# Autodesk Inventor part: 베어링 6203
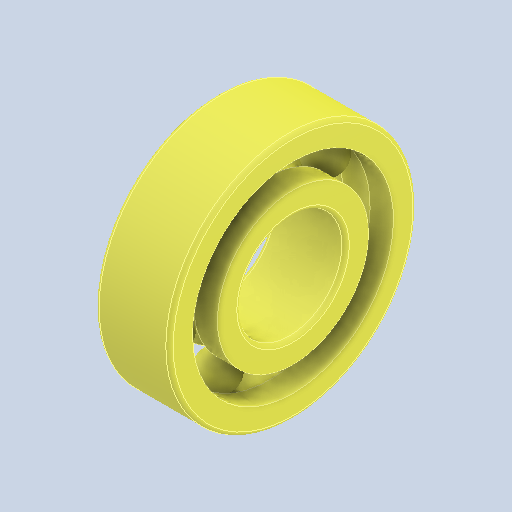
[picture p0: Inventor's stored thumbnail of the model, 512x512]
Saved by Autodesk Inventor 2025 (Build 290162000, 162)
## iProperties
Created: 2024-07
Part Number: 베어링 6203
Material: 강철, 연강
Description: 깊은 그루브 볼 베어링
Document SubType Name: Modeling
Designer: hsj03
Density: 7.86 g/cm^3
Appearance: 기본값
Author: jhkim
Revision Number: 1
Sending System: Autodesk Inventor 2025
Preprocessor: ST-DEVELOPER v20
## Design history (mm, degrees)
feature "Solid1"
feature "Solid1:1"
feature "Solid1:2"
feature "Solid1:3"
feature "Solid1:4"
feature "Solid1:5"
feature "Solid1:6"
feature "Solid1:7"
feature "Solid1:8"
node "솔리드1"
node "솔리드2"
node "솔리드3"
node "솔리드4"
node "솔리드5"
node "솔리드6"
node "솔리드7"
node "솔리드8"
node "솔리드9"
